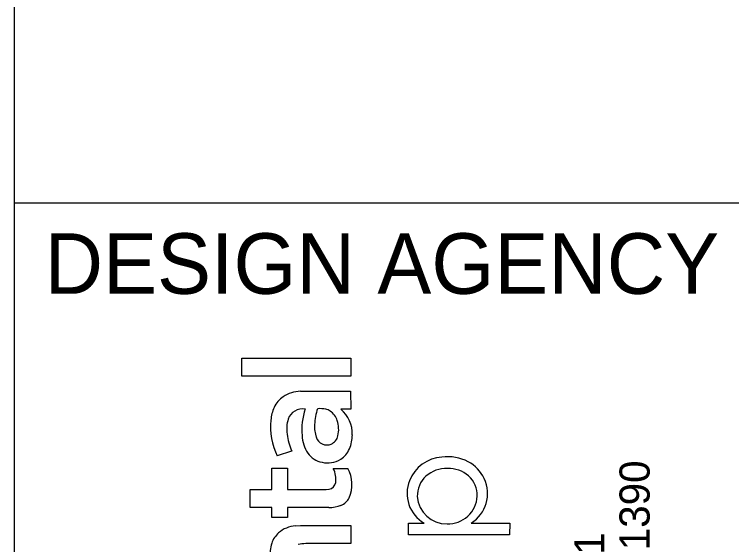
# Model space of a CAD drawing. Extents: x -0.4 to 34, y 0 to 22.
# Drawn here: x 32 to 33.185, y 3.936 to 4.812 of the extents above; entities that cross this region are included whole.
import ezdxf

# ---------------------------------------------------------------- set-up
doc = ezdxf.new("R2010")
doc.units = 0
doc.layers.add('SH_Cut_Line', color=7, linetype='Continuous')
doc.layers.add('SH_Data', color=7, linetype='Continuous')

msp = doc.modelspace()

# ---------------------------------------------------------------- linework, layer by layer
at = {"layer": 'SH_Cut_Line'}
for p, q in [((32.3756, 4.2141), (32.3756, 4.244)), ((32.3756, 4.244), (32.5557, 4.244)), ((32.5557, 4.244), (32.5557, 4.2141)), ((32.5557, 4.2141), (32.3756, 4.2141)), ((32.4727, 4.189), (32.5555, 4.1892)), ((32.5555, 4.1892), (32.5557, 4.1596)), ((32.5557, 4.1596), (32.5397, 4.1596)), ((32.4582, 4.0904), (32.4343, 4.0823)), ((32.4254, 4.027), (32.4255, 4.0621)), ((32.4255, 4.0621), (32.4511, 4.0621)), ((32.4511, 4.0621), (32.4512, 4.027)), ((32.527, 4.0616), (32.5511, 4.0616)), ((32.3896, 3.9972), (32.3896, 4.027)), ((32.3896, 4.027), (32.4254, 4.027)), ((32.4512, 4.027), (32.515, 4.027)), ((32.515, 4.027), (32.52, 4.0275)), ((32.4254, 3.9972), (32.3896, 3.9972)), ((32.4254, 3.9807), (32.4254, 3.9972)), ((32.5197, 3.9972), (32.4511, 3.9972)), ((32.4511, 3.9972), (32.4511, 3.9807)), ((32.4511, 3.9807), (32.4254, 3.9807)), ((32.6515, 3.9521), (32.6515, 3.9711)), ((32.6515, 3.9711), (32.6771, 3.9711)), ((32.7549, 3.9713), (32.8186, 3.9711)), ((32.8186, 3.9711), (32.8184, 3.9521)), ((32.4644, 3.9669), (32.4729, 3.9673)), ((32.4729, 3.9673), (32.5557, 3.9673)), ((32.5557, 3.9673), (32.5557, 3.9375)), ((32.8184, 3.9521), (32.6515, 3.9521)), ((32.5557, 3.9375), (32.4814, 3.9375))]:
    msp.add_line(p, q, dxfattribs=at)
msp.add_lwpolyline([(32.3756, 4.2141), (32.3756, 4.244), (32.5557, 4.244), (32.5557, 4.2141)], close=True, dxfattribs=at)
for points in [[(32.4727, 4.189), (32.5555, 4.1892), (32.5557, 4.1596)], [(32.5557, 4.1596), (32.5397, 4.1596)], [(32.4582, 4.0904), (32.4343, 4.0823)], [(32.5197, 3.9972), (32.4511, 3.9972), (32.4511, 3.9807), (32.4254, 3.9807), (32.4254, 3.9972), (32.3896, 3.9972), (32.3896, 4.027), (32.4254, 4.027), (32.4255, 4.0621), (32.4511, 4.0621), (32.4512, 4.027), (32.515, 4.027), (32.52, 4.0275)], [(32.527, 4.0616), (32.5511, 4.0616)], [(32.7549, 3.9713), (32.8186, 3.9711), (32.8184, 3.9521), (32.6515, 3.9521)], [(32.6515, 3.9521), (32.6515, 3.9711), (32.6771, 3.9711)], [(32.4644, 3.9669), (32.4729, 3.9673), (32.5557, 3.9673), (32.5557, 3.9375), (32.4814, 3.9375)]]:
    msp.add_lwpolyline(points, dxfattribs=at)
for centre, radius, start, end in [((32.4745, 4.1326), 0.0565, 91.8942, 122.6317), ((32.4745, 4.1326), 0.0565, 91.8942, 122.6317), ((32.4685, 4.1447), 0.043, 124.537, 155.6594), ((32.4685, 4.1447), 0.043, 124.537, 155.6594), ((32.4882, 4.1361), 0.0646, 155.9764, 175.3149), ((32.4882, 4.1361), 0.0646, 155.9764, 175.3149), ((32.5801, 4.1313), 0.0841, 159.8366, 178.0362), ((32.5801, 4.1313), 0.0841, 159.8366, 178.0362), ((32.5051, 4.1074), 0.053, 79.6696, 94.2322), ((32.5051, 4.1074), 0.053, 79.6696, 94.2322), ((32.4753, 4.1356), 0.024, 119.4252, 161.6629), ((32.4753, 4.1356), 0.024, 119.4252, 161.6629), ((32.4779, 4.1278), 0.0321, 85.3802, 116.6222), ((32.4779, 4.1278), 0.0321, 85.3802, 116.6222), ((32.5879, 4.1251), 0.1129, 162.0821, 184.5285), ((32.5879, 4.1251), 0.1129, 162.0821, 184.5285), ((32.5089, 4.1364), 0.0238, 56.8913, 76.2149), ((32.5089, 4.1364), 0.0238, 56.8913, 76.2149), ((32.5052, 4.1318), 0.0297, 17.5984, 55.7282), ((32.5052, 4.1318), 0.0297, 17.5984, 55.7282), ((32.5055, 4.1191), 0.0529, 358.0746, 49.762), ((32.5055, 4.1191), 0.0529, 358.0746, 49.762), ((32.5364, 4.1308), 0.113, 174.6101, 205.3899), ((32.5364, 4.1308), 0.113, 174.6101, 205.3899), ((32.5076, 4.1265), 0.0576, 163.1369, 188.1675), ((32.5076, 4.1265), 0.0576, 163.1369, 188.1675), ((32.4916, 4.1264), 0.0443, 345.9408, 18.9919), ((32.4916, 4.1264), 0.0443, 345.9408, 18.9919), ((32.5466, 4.1303), 0.0506, 175.5903, 199.8857), ((32.5466, 4.1303), 0.0506, 175.5903, 199.8857), ((32.5473, 4.1297), 0.0973, 186.7598, 203.7981), ((32.5473, 4.1297), 0.0973, 186.7598, 203.7981), ((32.5328, 4.1187), 0.0575, 182.5676, 213.7144), ((32.5328, 4.1187), 0.0575, 182.5676, 213.7144), ((32.5164, 4.1189), 0.0184, 198.2844, 293.3081), ((32.5164, 4.1189), 0.0184, 198.2844, 293.3081), ((32.5152, 4.1199), 0.0199, 295.2883, 347.4639), ((32.5152, 4.1199), 0.0199, 295.2883, 347.4639), ((32.5019, 4.1168), 0.0566, 336.016, 0.5951), ((32.5019, 4.1168), 0.0566, 336.016, 0.5951), ((32.5175, 4.1097), 0.0394, 303.4436, 336.18), ((32.5175, 4.1097), 0.0394, 303.4436, 336.18), ((32.5149, 4.1078), 0.0366, 215.0668, 259.8133), ((32.5149, 4.1078), 0.0366, 215.0668, 259.8133), ((32.7108, 4.0182), 0.0624, 93.9866, 158.3119), ((32.7108, 4.0182), 0.0624, 93.9866, 158.3119), ((32.7156, 4.0065), 0.0746, 62.6889, 97.0135), ((32.7156, 4.0065), 0.0746, 62.6889, 97.0135), ((32.5175, 4.1131), 0.0423, 257.5256, 300.882), ((32.5175, 4.1131), 0.0423, 257.5256, 300.882), ((32.7212, 4.0191), 0.0608, 25.0657, 61.9602), ((32.7212, 4.0191), 0.0608, 25.0657, 61.9602), ((32.4863, 4.042), 0.0452, 10.1545, 25.723), ((32.4863, 4.042), 0.0452, 10.1545, 25.723), ((32.503, 4.0351), 0.0549, 336.589, 28.8991), ((32.503, 4.0351), 0.0549, 336.589, 28.8991), ((32.7138, 4.0102), 0.0513, 87.8965, 131.1812), ((32.7138, 4.0102), 0.0513, 87.8965, 131.1812), ((32.7175, 4.0102), 0.0513, 49.9089, 92.0363), ((32.7175, 4.0102), 0.0513, 49.9089, 92.0363), ((32.4957, 4.0436), 0.0356, 351.914, 10.2059), ((32.4957, 4.0436), 0.0356, 351.914, 10.2059), ((32.7092, 4.0167), 0.0434, 132.3289, 182.0949), ((32.7092, 4.0167), 0.0434, 132.3289, 182.0949), ((32.7215, 4.0173), 0.0433, 358.0487, 47.9447), ((32.7215, 4.0173), 0.0433, 358.0487, 47.9447), ((32.7245, 4.02), 0.0574, 301.9776, 25.6418), ((32.7245, 4.02), 0.0574, 301.9776, 25.6418), ((32.5184, 4.04), 0.0126, 277.6142, 353.7918), ((32.5184, 4.04), 0.0126, 277.6142, 353.7918), ((32.707, 4.0202), 0.0581, 158.656, 198.171), ((32.707, 4.0202), 0.0581, 158.656, 198.171), ((32.5291, 4.0261), 0.0275, 292.6889, 332.0598), ((32.5291, 4.0261), 0.0275, 292.6889, 332.0598), ((32.7135, 4.0181), 0.0478, 183.5974, 271.7045), ((32.7135, 4.0181), 0.0478, 183.5974, 271.7045), ((32.7172, 4.018), 0.0477, 267.3149, 357.4019), ((32.7172, 4.018), 0.0477, 267.3149, 357.4019), ((32.5209, 4.0486), 0.0514, 268.6727, 291.5235), ((32.5209, 4.0486), 0.0514, 268.6727, 291.5235), ((32.7103, 4.0243), 0.0627, 200.8399, 238.0162), ((32.7103, 4.0243), 0.0627, 200.8399, 238.0162), ((32.4687, 3.9172), 0.0499, 94.9706, 130.2248), ((32.4687, 3.9172), 0.0499, 94.9706, 130.2248), ((32.4635, 3.9255), 0.0402, 132.2238, 161.6823), ((32.4635, 3.9255), 0.0402, 132.2238, 161.6823), ((32.4787, 3.9211), 0.056, 162.274, 187.7917), ((32.4787, 3.9211), 0.056, 162.274, 187.7917), ((32.4811, 3.8915), 0.046, 89.6051, 105.3303), ((32.4811, 3.8915), 0.046, 89.6051, 105.3303)]:
    msp.add_arc(centre, radius, start, end, dxfattribs=at)
at = {"layer": 'SH_Data'}
for p, q in [((32, 0.5), (32, 21.5)), ((32, 4.5), (33.5, 4.5))]:
    msp.add_line(p, q, dxfattribs=at)

# ---------------------------------------------------------------- texts
at = {"layer": 'SH_Cut_Line'}
msp.add_text('DESIGN AGENCY', height=0.1, dxfattribs=at).set_placement((32.05, 4.35))
for s, p in [('800.835.1390', (33.0497, 3.6671)), ('450 GRANT ST., AKRON, OH  44311', (32.9749, 2.8374))]:
    msp.add_text(s, height=0.049846, rotation=90, dxfattribs=at).set_placement(p)

doc.saveas('drawing.dxf')
